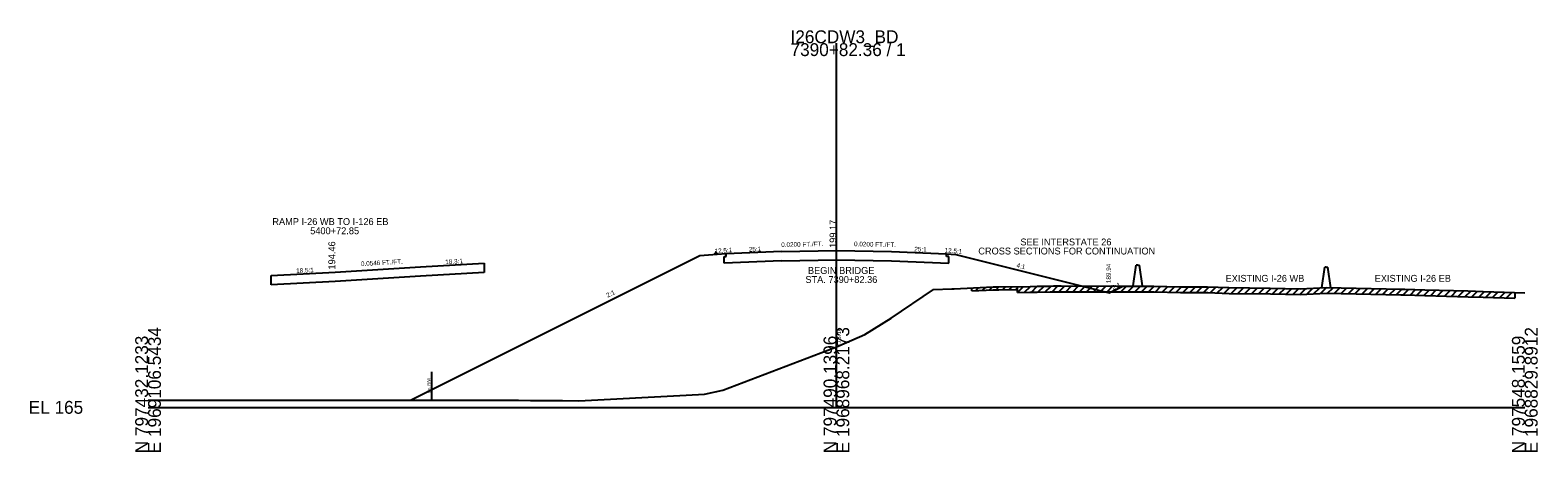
# Model space of a CAD drawing. Extents: x -26 to 1968923, y -11 to 797553.
# Drawn here: x -25.7 to 302.8, y 490.3 to 582.2 of the extents above; entities that cross this region are included whole.
import ezdxf

# ---------------------------------------------------------------- set-up
doc = ezdxf.new("R2010")
doc.units = 0
for name, color, linetype in [('RD_GPK_XS_Cell', 7, 'Continuous'), ('RD_XS_Base', 7, 'Continuous'), ('RD_XS_Bridge', 7, 'Continuous'), ('RD_XS_CurbTop', 7, 'Continuous'), ('RD_XS_EarthShd', 7, 'Continuous'), ('RD_XS_ExGround', 7, 'Continuous'), ('RD_XS_ExPaveRet', 7, 'Continuous'), ('RD_XS_ExRW', 7, 'Continuous'), ('RD_XS_MedBWall', 7, 'Continuous'), ('RD_XS_Misc_Line', 7, 'Continuous'), ('RD_XS_Pave', 7, 'Continuous'), ('RD_XS_PaveShd', 7, 'Continuous'), ('RD_XS_TieSlope', 7, 'Continuous'), ('RD_XS_TX_Elev_EX', 7, 'Continuous'), ('RD_XS_TX_Elev_PR', 7, 'Continuous'), ('RD_XS_TX_Notes', 7, 'Continuous'), ('RD_XS_TX_Profile', 7, 'Continuous'), ('RD_XS_TX_ShdSlope', 7, 'Continuous'), ('RD_XS_TX_Slope', 7, 'Continuous'), ('RD_XS_TX_Station', 7, 'Continuous')]:
    doc.layers.add(name, color=color, linetype=linetype)

msp = doc.modelspace()

# ---------------------------------------------------------------- linework, layer by layer
at = {"layer": 'RD_GPK_XS_Cell'}
for p, q in [((150, 500), (150, 579.32)), ((0, 500), (150, 500)), ((150, 500), (300, 500))]:
    msp.add_line(p, q, dxfattribs=at)
at = {"layer": 'RD_XS_Base'}
for p, q in [((125.5, 532.87), (126, 532.89)), ((125.5, 531.39), (125.5, 532.87)), ((126, 532.89), (126, 533.45)), ((174, 532.89), (174, 533.45)), ((174.5, 532.87), (174, 532.89)), ((174.5, 531.39), (174.5, 532.87)), ((138, 531.89), (125.5, 531.39)), ((138, 531.89), (150, 532.13)), ((150, 532.13), (162, 531.89)), ((162, 531.89), (174.5, 531.39))]:
    msp.add_line(p, q, dxfattribs=at)
at = {"layer": 'RD_XS_Bridge'}
for p, q in [((26.8, 528.71), (40.79, 529.46)), ((40.79, 529.46), (59.35, 530.63)), ((59.35, 530.63), (73.21, 531.39)), ((73.21, 529.35), (59.35, 528.59)), ((73.21, 531.39), (73.21, 529.35)), ((26.8, 526.67), (26.8, 528.71)), ((40.79, 527.42), (26.8, 526.67)), ((59.35, 528.59), (40.79, 527.42))]:
    msp.add_line(p, q, dxfattribs=at)
at = {"layer": 'RD_XS_CurbTop'}
for p, q in [((123.53, 533.26), (123.59, 533.69)), ((124, 533.29), (123.53, 533.26)), ((124, 533.29), (123.75, 533.75))]:
    msp.add_line(p, q, dxfattribs=at)
msp.add_ellipse((123.68, 533.67), major_axis=(0, 0.131), ratio=0.686, start_param=5.388101, end_param=7.661995, dxfattribs=at)
at = {"layer": 'RD_XS_EarthShd'}
for p, q in [((126, 533.45), (124, 533.29)), ((174, 533.45), (176, 533.29))]:
    msp.add_line(p, q, dxfattribs=at)
at = {"layer": 'RD_XS_ExGround'}
msp.add_lwpolyline([(0, 501.54), (0.37, 501.54), (4.63, 501.54), (13.98, 501.54), (19.16, 501.54), (19.56, 501.54), (27.71, 501.54), (32.91, 501.54), (38.49, 501.54), (44.14, 501.54), (67.09, 501.54), (73.5, 501.54), (75.49, 501.54), (77.48, 501.54), (80.69, 501.55), (83.3, 501.51), (88.31, 501.48), (90.29, 501.47), (93.84, 501.44), (117.28, 502.67), (121.22, 502.86), (125.28, 503.71), (149.64, 513), (150, 513.16), (156.17, 515.84), (161.94, 519.43), (171.18, 525.67), (175.13, 525.78), (175.63, 525.79), (177.02, 525.87), (184.15, 526.24), (184.68, 526.22), (185.41, 526.23), (192.19, 526.35), (193.72, 526.37), (196.5, 526.42), (197.28, 526.44), (198.97, 526.44), (205.58, 526.43), (209.92, 526.44), (211.53, 526.42), (219.19, 526.39), (224.93, 526.28), (230.88, 526.25), (235.52, 526.08), (244.54, 525.98), (251.13, 525.84), (256.72, 526.09), (273.05, 525.74), (273.84, 525.74), (278.23, 525.63), (287.58, 525.35), (290.94, 525.25), (293.26, 525.17), (300, 524.94)], dxfattribs=at)
at = {"layer": 'RD_XS_ExPaveRet'}
for p, q in [((179.49, 525.37), (179.49, 526)), ((189.49, 525.05), (189.49, 526.3)), ((189.49, 525.05), (192.16, 525.1)), ((192.16, 525.1), (193.72, 525.12)), ((193.72, 525.12), (196.55, 525.18)), ((196.55, 525.18), (197.28, 525.19)), ((197.28, 525.19), (198.85, 525.19)), ((198.85, 525.19), (205.54, 525.18)), ((205.54, 525.18), (209.94, 525.19)), ((209.94, 525.19), (211.57, 525.17)), ((211.57, 525.17), (219.22, 525.14)), ((219.22, 525.14), (224.99, 525.03)), ((224.99, 525.03), (230.93, 525)), ((230.93, 525), (235.58, 524.83)), ((235.58, 524.83), (244.58, 524.73)), ((244.58, 524.73), (251.15, 524.59)), ((251.15, 524.59), (256.74, 524.84)), ((256.74, 524.84), (273.01, 524.5)), ((273.01, 524.5), (273.81, 524.49)), ((273.81, 524.49), (278.23, 524.38)), ((278.23, 524.38), (287.65, 524.1)), ((287.65, 524.1), (290.94, 524.01)), ((290.94, 524.01), (293.21, 523.92)), ((293.21, 523.92), (297.82, 523.77)), ((297.82, 525.02), (297.82, 523.77))]:
    msp.add_line(p, q, dxfattribs=at)
msp.add_lwpolyline([(179.49, 525.37), (184.16, 525.62), (184.67, 525.6), (185.42, 525.6), (189.49, 525.68)], dxfattribs=at)
at = {"layer": 'RD_XS_ExRW'}
msp.add_line((61.74, 507.76), (61.74, 501.76), dxfattribs=at)
at = {"layer": 'RD_XS_MedBWall'}
for p, q in [((214.68, 526.48), (215.34, 530.96)), ((215.68, 530.96), (215.34, 530.96)), ((215.68, 530.96), (216.01, 530.96)), ((216.68, 526.48), (216.01, 530.96)), ((255.74, 526.02), (256.41, 530.5)), ((256.74, 530.5), (256.41, 530.5)), ((256.74, 530.5), (257.08, 530.5)), ((257.74, 526.02), (257.08, 530.5))]:
    msp.add_line(p, q, dxfattribs=at)
at = {"layer": 'RD_XS_Misc_Line'}
for p, q in [((179.49, 525.96), (179.54, 526)), ((180.37, 525.42), (181.03, 526.08)), ((181.86, 525.5), (182.52, 526.16)), ((183.35, 525.58), (184.01, 526.24)), ((184.79, 525.6), (185.42, 526.23)), ((186.22, 525.62), (186.86, 526.25)), ((187.66, 525.64), (188.3, 526.28)), ((189.1, 525.67), (189.49, 526.06)), ((189.49, 525.05), (190.76, 526.32)), ((190.99, 525.08), (192.26, 526.35)), ((192.49, 525.1), (193.76, 526.37)), ((193.99, 525.13), (195.27, 526.4)), ((195.49, 525.16), (196.77, 526.43)), ((196.99, 525.19), (198.25, 526.44)), ((198.49, 525.19), (199.74, 526.44)), ((199.99, 525.19), (201.24, 526.44)), ((201.49, 525.19), (202.74, 526.44)), ((202.99, 525.19), (204.24, 526.44)), ((204.49, 525.18), (205.74, 526.43)), ((205.99, 525.18), (207.24, 526.44)), ((207.49, 525.19), (208.74, 526.44)), ((208.99, 525.19), (210.24, 526.44)), ((210.49, 525.18), (211.73, 526.42)), ((211.99, 525.17), (213.24, 526.41)), ((213.49, 525.16), (214.74, 526.41)), ((214.99, 525.16), (216.24, 526.4)), ((216.49, 525.15), (217.74, 526.4)), ((217.99, 525.15), (219.24, 526.39)), ((219.49, 525.14), (220.72, 526.36)), ((220.99, 525.11), (222.22, 526.34)), ((222.49, 525.08), (223.72, 526.31)), ((223.99, 525.05), (225.22, 526.28)), ((225.49, 525.03), (226.73, 526.27)), ((226.99, 525.02), (228.23, 526.27)), ((228.49, 525.01), (229.73, 526.26)), ((229.99, 525), (231.23, 526.24)), ((231.49, 524.98), (232.7, 526.19)), ((232.99, 524.92), (234.2, 526.13)), ((234.49, 524.87), (235.7, 526.08)), ((235.99, 524.83), (237.23, 526.06)), ((237.49, 524.81), (238.73, 526.05)), ((238.99, 524.79), (240.23, 526.03)), ((240.49, 524.78), (241.73, 526.01)), ((241.99, 524.76), (243.23, 525.99)), ((243.49, 524.74), (244.73, 525.98)), ((244.99, 524.72), (246.22, 525.94)), ((246.49, 524.69), (247.72, 525.91)), ((247.99, 524.65), (249.22, 525.88)), ((249.49, 524.62), (250.72, 525.85)), ((250.99, 524.59), (252.29, 525.89)), ((252.49, 524.65), (253.8, 525.96)), ((253.99, 524.72), (255.3, 526.03)), ((255.49, 524.79), (256.8, 526.09)), ((256.99, 524.84), (258.22, 526.06)), ((258.49, 524.81), (259.72, 526.03)), ((259.99, 524.77), (261.22, 526)), ((261.49, 524.74), (262.72, 525.97)), ((262.99, 524.71), (264.22, 525.93)), ((264.49, 524.68), (265.72, 525.9)), ((265.99, 524.65), (267.22, 525.87)), ((267.49, 524.61), (268.72, 525.84)), ((268.99, 524.58), (270.22, 525.81)), ((270.49, 524.55), (271.72, 525.77)), ((271.99, 524.52), (273.22, 525.74)), ((273.49, 524.49), (274.72, 525.72)), ((274.99, 524.46), (276.21, 525.68)), ((276.49, 524.42), (277.71, 525.64)), ((277.99, 524.39), (279.21, 525.6)), ((279.49, 524.34), (280.71, 525.56)), ((280.99, 524.3), (282.21, 525.51)), ((282.49, 524.25), (283.71, 525.47)), ((283.99, 524.21), (285.21, 525.42)), ((285.49, 524.16), (286.71, 525.38)), ((286.99, 524.12), (288.21, 525.33)), ((288.49, 524.08), (289.71, 525.29)), ((289.99, 524.03), (291.21, 525.25)), ((291.49, 523.99), (292.7, 525.19)), ((292.99, 523.93), (294.2, 525.14)), ((294.49, 523.88), (295.7, 525.09)), ((295.99, 523.83), (297.2, 525.04))]:
    msp.add_line(p, q, dxfattribs=at)
at = {"layer": 'RD_XS_Pave'}
for p, q in [((138, 533.93), (150, 534.17)), ((150, 534.17), (162, 533.93))]:
    msp.add_line(p, q, dxfattribs=at)
at = {"layer": 'RD_XS_PaveShd'}
for p, q in [((138, 533.93), (126, 533.45)), ((162, 533.93), (174, 533.45))]:
    msp.add_line(p, q, dxfattribs=at)
at = {"layer": 'RD_XS_TieSlope'}
for p, q in [((120.25, 532.99), (57.33, 501.54)), ((124, 533.29), (120.25, 532.99)), ((176, 533.29), (209.44, 524.94)), ((209.44, 524.94), (212.39, 526.41))]:
    msp.add_line(p, q, dxfattribs=at)

# ---------------------------------------------------------------- texts
at = {"layer": 'RD_GPK_XS_Cell'}
for s, p in [('I26CDW3_BD', (140, 579.32)), ('7390+82.36 / 1', (140, 576.52)), ('EL 165', (-26, 498.6))]:
    msp.add_text(s, height=2.8, dxfattribs=at).set_placement(p)
for s, p in [('E 1969106.5434', (2.8, 490)), ('E 1968968.2173', (152.8, 490)), ('E 1968829.8912', (302.8, 490)), ('N 797432.1233', (0, 490)), ('N 797490.1396', (150, 490)), ('N 797548.1559', (300, 490))]:
    msp.add_text(s, height=2.8, rotation=90, dxfattribs=at).set_placement(p)
at = {"layer": 'RD_XS_ExRW'}
msp.add_text('Ex. R/W ', height=0.65, rotation=90, dxfattribs=at).set_placement((61.49, 503.14))
at = {"layer": 'RD_XS_TX_Elev_EX'}
msp.add_text('178.16', height=1, rotation=90, dxfattribs=at).set_placement((151, 513.16))
at = {"layer": 'RD_XS_TX_Elev_PR'}
for s, p in [(' 199.17', (150, 534.17)), (' 194.46', (40.79, 529.46))]:
    msp.add_text(s, height=1.5, rotation=90, dxfattribs=at).set_placement(p)
at = {"layer": 'RD_XS_TX_Notes'}
for s, p in [('SEE INTERSTATE 26', (190.08, 535.27)), ('CROSS SECTIONS FOR CONTINUATION', (180.91, 533.3)), ('BEGIN BRIDGE', (143.79, 529.06)), ('STA. 7390+82.36', (143.24, 527.09)), ('EXISTING I-26 WB', (234.79, 527.35)), ('EXISTING I-26 EB', (267.29, 527.35))]:
    msp.add_text(s, height=1.5, dxfattribs=at).set_placement(p)
at = {"layer": 'RD_XS_TX_Profile'}
for s, rotation, p in [('18.3:1', 3.1226, (64.79, 531.18)), ('25:1', 2.2906, (130.94, 533.9)), ('25:1', 357.7094, (166.96, 533.99)), ('18.5:1', 3.0943, (32.3, 529.25))]:
    msp.add_text(s, height=1, rotation=rotation, dxfattribs=at).set_placement(p)
at = {"layer": 'RD_XS_TX_ShdSlope'}
for rotation, p in [(4.5739, (123.5, 533.51)), (355.4261, (173.54, 533.74))]:
    msp.add_text('12.5:1', height=1, rotation=rotation, dxfattribs=at).set_placement(p)
at = {"layer": 'RD_XS_TX_Slope'}
for s, rotation, p in [('0.0200 FT./FT.', 1.1458, (137.98, 534.93)), ('0.0200 FT./FT.', 358.8542, (153.83, 535.1)), ('0.0546 FT./FT.', 3.1226, (46.41, 530.77)), ('4:1', 345.9638, (189.15, 530.52)), ('189.94', 90, (209.79, 527.06)), ('2:1', 25.5405, (210.32, 525.55)), ('2:1', 25.5405, (100.14, 523.87))]:
    msp.add_text(s, height=1, rotation=rotation, dxfattribs=at).set_placement(p)
at = {"layer": 'RD_XS_TX_Station'}
for s, p in [('RAMP I-26 WB TO I-126 EB', (27.08, 539.71)), ('5400+72.85', (35.33, 537.71))]:
    msp.add_text(s, height=1.5, dxfattribs=at).set_placement(p)

doc.saveas('drawing.dxf')
